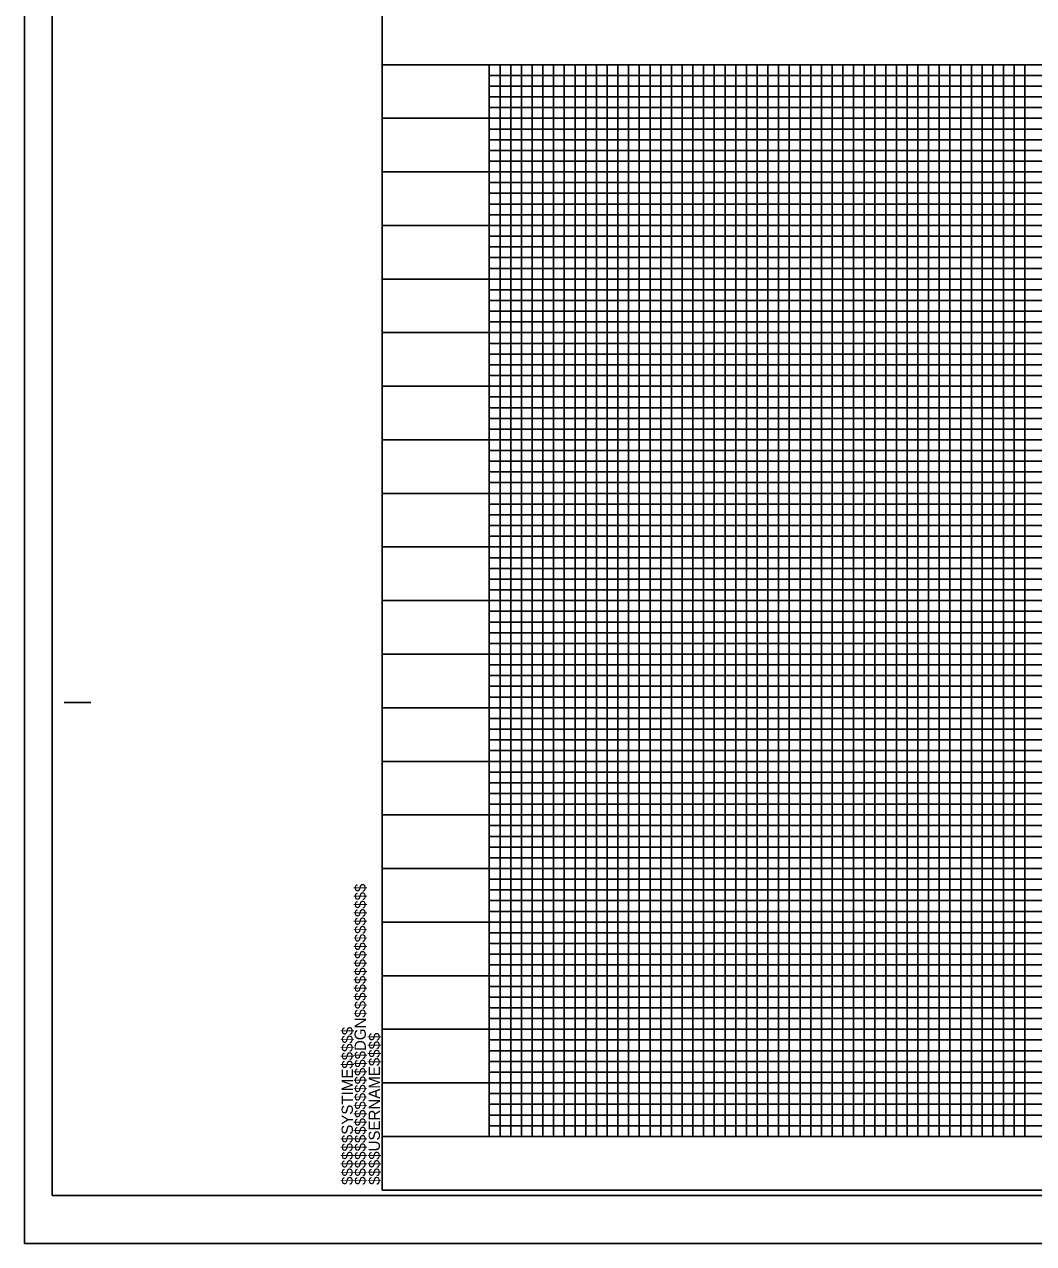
# Model space of a CAD drawing. Extents: x 553912 to 567693, y 512355 to 537539.
# Drawn here: x 565534 to 566005, y 513390 to 513959 of the extents above; entities that cross this region are included whole.
import ezdxf

# ---------------------------------------------------------------- set-up
doc = ezdxf.new("R2010")
doc.units = 0
for name, color, linetype in [('Sheet Cutting Line CELL', 7, 'Continuous'), ('Sheet DOT Grid CELL', 7, 'Continuous'), ('Sheet Layout Profile Border Port 2', 7, 'Continuous'), ('Sheet Plot Border Inside CELL', 7, 'Continuous'), ('Sheet Plot Border Outside CELL', 7, 'Continuous'), ('Sheet Profile CELL', 7, 'Continuous'), ('Sheet Profile Grid Major CELL', 7, 'Continuous'), ('Sheet Profile Grid Middle CELL', 7, 'Continuous'), ('Sheet Profile Grid Minor CELL', 7, 'Continuous')]:
    doc.layers.add(name, color=color, linetype=linetype)

msp = doc.modelspace()

# ---------------------------------------------------------------- linework, layer by layer
at = {"layer": 'Sheet Cutting Line CELL'}
for p, q in [((565534.35, 514489.72), (565534.35, 513389.72)), ((565534.35, 513389.72), (567218.35, 513389.72))]:
    msp.add_line(p, q, dxfattribs=at)
at = {"layer": 'Sheet DOT Grid CELL'}
for p, q in [((565701.35, 513939.72), (567201.24, 513939.72)), ((565751.35, 513939.72), (565751.35, 513439.72)), ((565801.35, 513939.72), (565801.35, 513439.72)), ((565851.35, 513939.72), (565851.35, 513439.72)), ((565901.35, 513939.72), (565901.35, 513439.72)), ((565951.35, 513939.72), (565951.35, 513439.72)), ((566001.35, 513939.72), (566001.35, 513439.72)), ((565701.35, 513889.72), (567201.24, 513889.72)), ((565701.35, 513839.72), (567201.24, 513839.72)), ((565701.35, 513789.72), (567201.24, 513789.72)), ((565701.35, 513739.72), (567201.24, 513739.72)), ((565701.35, 513689.72), (567201.24, 513689.72)), ((565701.35, 513639.72), (567201.24, 513639.72)), ((565701.35, 513589.72), (567201.24, 513589.72)), ((565701.35, 513539.72), (567201.24, 513539.72)), ((565701.35, 513489.72), (567201.24, 513489.72))]:
    msp.add_line(p, q, dxfattribs=at)
at = {"layer": 'Sheet Layout Profile Border Port 2'}
msp.add_lwpolyline([(565751.35, 513939.72), (567151.35, 513939.72), (567151.35, 513439.72), (565751.35, 513439.72)], close=True, dxfattribs=at)
at = {"layer": 'Sheet Plot Border Inside CELL'}
msp.add_lwpolyline([(565547.35, 513412.17), (567213.85, 513412.17), (567213.85, 514467.27), (565547.35, 514467.27)], close=True, dxfattribs=at)
at = {"layer": 'Sheet Plot Border Outside CELL'}
msp.add_lwpolyline([(565534.35, 513389.72), (567218.35, 513389.72), (567218.35, 514489.72), (565534.35, 514489.72)], close=True, dxfattribs=at)
at = {"layer": 'Sheet Profile CELL'}
for p, q in [((565701.35, 513939.72), (567201.35, 513939.72)), ((565552.85, 513642.22), (565565.35, 513642.22)), ((567201.35, 513439.72), (565701.35, 513439.72)), ((565701.35, 513414.72), (567201.35, 513414.72)), ((565701.35, 513414.72), (565701.35, 513414.72)), ((565701.35, 513414.72), (565701.35, 513414.72)), ((565701.35, 513414.72), (565701.35, 513414.72)), ((565701.35, 513414.72), (565701.35, 513414.72)), ((565701.35, 513414.72), (565701.35, 513414.72)), ((565701.35, 513414.72), (565701.35, 513414.72)), ((565701.35, 513414.72), (565701.35, 513414.72))]:
    msp.add_line(p, q, dxfattribs=at)
msp.add_lwpolyline([(567201.35, 514464.72), (565701.35, 514464.72), (565701.35, 513414.72), (567201.35, 513414.72)], close=True, dxfattribs=at)
msp.add_lwpolyline([(565738.85, 513414.72), (565738.85, 513414.72)], dxfattribs=at)
at = {"layer": 'Sheet Profile Grid Major CELL'}
msp.add_line((565701.35, 513439.72), (565701.35, 513439.72), dxfattribs=at)
for points in [[(565751.35, 513939.72), (565751.35, 513439.72), (565801.35, 513439.72), (565801.35, 513939.72), (565851.35, 513939.72), (565851.35, 513439.72), (565901.35, 513439.72), (565901.35, 513939.72), (565951.35, 513939.72), (565951.35, 513439.72), (566001.35, 513439.72), (566001.35, 513939.72), (566051.35, 513939.72)], [(567201.35, 513889.72), (565701.35, 513889.72)], [(567201.35, 513839.72), (565701.35, 513839.72), (565701.35, 513789.72), (567201.35, 513789.72)], [(567201.35, 513739.72), (565701.35, 513739.72), (565701.35, 513689.72), (567201.35, 513689.72)], [(567201.35, 513639.72), (565701.35, 513639.72), (565701.35, 513589.72), (567201.35, 513589.72)], [(567201.35, 513539.72), (565701.35, 513539.72), (565701.35, 513539.72), (565701.35, 513489.72), (567201.35, 513489.72)], [(567201.35, 513439.72), (565701.35, 513439.72)]]:
    msp.add_lwpolyline(points, dxfattribs=at)
at = {"layer": 'Sheet Profile Grid Middle CELL'}
for points in [[(565726.35, 513939.72), (565776.35, 513939.72), (565776.35, 513439.72), (565826.35, 513439.72), (565826.35, 513939.72), (565876.35, 513939.72), (565876.35, 513439.72), (565926.35, 513439.72), (565926.35, 513939.72), (565976.35, 513939.72), (565976.35, 513439.72), (566026.35, 513439.72)], [(565701.35, 513914.72), (567201.35, 513914.72)], [(567201.35, 513864.72), (565701.35, 513864.72), (565701.35, 513814.72), (567201.35, 513814.72)], [(567201.35, 513764.72), (565701.35, 513764.72), (565701.35, 513714.72), (567201.35, 513714.72)], [(567201.35, 513664.72), (565701.35, 513664.72), (565701.35, 513614.72), (567201.35, 513614.72)], [(567201.35, 513564.72), (565701.35, 513564.72), (565701.35, 513514.72), (567201.35, 513514.72)], [(567201.35, 513464.72), (565701.35, 513464.72)]]:
    msp.add_lwpolyline(points, dxfattribs=at)
at = {"layer": 'Sheet Profile Grid Minor CELL'}
for p, q in [((565751.35, 513934.72), (567151.35, 513934.72)), ((567151.35, 513929.72), (565751.35, 513929.72)), ((565751.35, 513924.72), (567151.35, 513924.72)), ((567151.35, 513919.72), (565751.35, 513919.72)), ((565751.35, 513909.72), (567151.35, 513909.72)), ((567151.35, 513904.72), (565751.35, 513904.72)), ((565751.35, 513899.72), (567151.35, 513899.72)), ((567151.35, 513894.72), (565751.35, 513894.72)), ((565751.35, 513884.72), (567151.35, 513884.72)), ((567151.35, 513879.72), (565751.35, 513879.72)), ((565751.35, 513874.72), (567151.35, 513874.72)), ((567151.35, 513869.72), (565751.35, 513869.72)), ((565751.35, 513859.72), (567151.35, 513859.72)), ((567151.35, 513854.72), (565751.35, 513854.72)), ((565751.35, 513849.72), (567151.35, 513849.72)), ((567151.35, 513844.72), (565751.35, 513844.72)), ((565751.35, 513834.72), (567151.35, 513834.72)), ((567151.35, 513829.72), (565751.35, 513829.72)), ((565751.35, 513824.72), (567151.35, 513824.72)), ((567151.35, 513819.72), (565751.35, 513819.72)), ((565751.35, 513809.72), (567151.35, 513809.72)), ((567151.35, 513804.72), (565751.35, 513804.72)), ((565751.35, 513799.72), (567151.35, 513799.72)), ((567151.35, 513794.72), (565751.35, 513794.72)), ((565751.35, 513784.72), (567151.35, 513784.72)), ((567151.35, 513779.72), (565751.35, 513779.72)), ((565751.35, 513774.72), (567151.35, 513774.72)), ((567151.35, 513769.72), (565751.35, 513769.72)), ((565751.35, 513759.72), (567151.35, 513759.72)), ((567151.35, 513754.72), (565751.35, 513754.72)), ((565751.35, 513749.72), (567151.35, 513749.72)), ((567151.35, 513744.72), (565751.35, 513744.87)), ((565751.35, 513734.72), (567151.35, 513734.72)), ((567151.35, 513729.72), (565751.35, 513729.72)), ((565751.35, 513724.72), (567151.35, 513724.72)), ((567151.35, 513719.72), (565751.35, 513719.72)), ((565751.35, 513709.72), (567151.35, 513709.72)), ((567151.35, 513704.72), (565751.35, 513704.72)), ((565751.35, 513699.72), (567151.35, 513699.72)), ((567151.35, 513694.72), (565751.35, 513694.72)), ((565751.35, 513684.72), (567151.35, 513684.72)), ((567151.35, 513679.72), (565751.35, 513679.72)), ((565751.35, 513674.72), (567151.35, 513674.72)), ((567151.35, 513669.72), (565751.35, 513669.72)), ((565751.35, 513659.72), (567151.35, 513659.72)), ((567151.35, 513654.72), (565751.35, 513654.72)), ((565751.35, 513649.72), (567151.35, 513649.72)), ((567151.35, 513644.72), (565751.35, 513644.72)), ((565751.35, 513634.72), (567151.35, 513634.72)), ((567151.35, 513629.72), (565751.35, 513629.72)), ((565751.35, 513624.72), (567151.35, 513624.72)), ((567151.35, 513619.72), (565751.35, 513619.72)), ((565751.35, 513609.72), (567151.35, 513609.72)), ((567151.35, 513604.72), (565751.35, 513604.72)), ((565751.35, 513599.72), (567151.35, 513599.72)), ((567151.35, 513594.72), (565751.35, 513594.72)), ((565751.35, 513584.72), (567151.35, 513584.72)), ((567151.35, 513579.72), (565751.35, 513579.72)), ((565751.35, 513574.72), (567151.35, 513574.72)), ((567151.35, 513569.72), (565751.35, 513569.72)), ((565751.35, 513559.72), (567151.35, 513559.72)), ((567151.35, 513554.72), (565751.35, 513554.72)), ((565751.35, 513549.72), (567151.35, 513549.72)), ((567151.35, 513544.72), (565751.35, 513544.72)), ((565751.35, 513534.72), (567151.35, 513534.72)), ((567151.35, 513529.72), (565751.35, 513529.72)), ((565751.35, 513524.72), (567151.35, 513524.72)), ((567151.35, 513519.72), (565751.35, 513519.72)), ((565751.35, 513509.72), (567151.35, 513509.72)), ((567151.35, 513504.72), (565751.35, 513504.72)), ((565751.35, 513499.72), (567151.35, 513499.72)), ((567151.35, 513494.72), (565751.35, 513494.72)), ((565751.35, 513484.72), (567151.35, 513484.72)), ((567151.35, 513479.72), (565751.35, 513479.72)), ((565751.35, 513474.72), (567151.35, 513474.72)), ((567151.35, 513469.72), (565751.35, 513469.72)), ((565751.35, 513459.72), (567151.35, 513459.72)), ((567151.35, 513454.72), (565751.35, 513454.72)), ((565751.35, 513449.72), (567151.35, 513449.72)), ((565751.35, 513444.72), (567151.35, 513444.72))]:
    msp.add_line(p, q, dxfattribs=at)
for points in [[(565751.35, 513939.72), (565756.35, 513939.72), (565756.35, 513439.72), (565761.35, 513439.72), (565761.35, 513939.72), (565766.35, 513939.72), (565766.35, 513439.72), (565771.35, 513439.72), (565771.35, 513939.72), (565781.35, 513939.72), (565781.35, 513439.72), (565786.35, 513439.72), (565786.35, 513939.72), (565791.35, 513939.72), (565791.35, 513439.72), (565796.35, 513439.72), (565806.35, 513439.72), (565811.35, 513439.72), (565811.35, 513939.72), (565816.35, 513939.72), (565816.35, 513439.72), (565821.35, 513439.72), (565821.35, 513939.72), (565831.35, 513939.72), (565831.35, 513439.72), (565836.35, 513439.72), (565836.35, 513939.72), (565841.35, 513939.72), (565841.35, 513439.72), (565846.35, 513439.72), (565846.35, 513939.72), (565856.35, 513939.72), (565856.35, 513439.72), (565861.35, 513439.72), (565861.35, 513939.72), (565866.35, 513939.72), (565866.35, 513439.72), (565871.35, 513439.72), (565871.35, 513939.72), (565881.35, 513939.72), (565881.35, 513439.72), (565886.35, 513439.72), (565886.35, 513939.72), (565891.35, 513939.72), (565891.35, 513439.72), (565896.35, 513439.72), (565896.35, 513939.72), (565906.35, 513939.72), (565906.35, 513439.72), (565911.35, 513439.72), (565911.35, 513939.72), (565916.35, 513939.72), (565916.35, 513439.72), (565921.35, 513439.72), (565921.35, 513939.72), (565931.35, 513939.72), (565931.35, 513439.72), (565936.35, 513439.72), (565936.35, 513939.72), (565941.35, 513939.72), (565941.35, 513439.72), (565946.35, 513439.72), (565946.35, 513939.72), (565956.35, 513939.72), (565956.35, 513439.72), (565961.35, 513439.72), (565961.35, 513939.72), (565966.35, 513939.72), (565966.35, 513439.72)], [(565796.35, 513439.72), (565796.35, 513939.72), (565806.35, 513939.72), (565806.35, 513439.72)], [(565966.35, 513439.72), (565971.35, 513439.72), (565971.35, 513939.72), (565981.35, 513939.72), (565981.35, 513439.72), (565986.35, 513439.72), (565986.35, 513939.72), (565991.35, 513939.72), (565991.35, 513439.72), (565996.35, 513439.72), (565996.35, 513939.72), (566006.35, 513939.72)]]:
    msp.add_lwpolyline(points, dxfattribs=at)

# ---------------------------------------------------------------- texts
at = {"layer": 'Sheet Profile CELL'}
for s, p in [('$$$$$$$$$$$$$$$$DGN$$$$$$$$$$$$$$$$', (565693.72, 513417.09)), ('$$$$$$SYSTIME$$$$$', (565687.67, 513417.09)), ('$$$$USERNAME$$$$', (565700.29, 513417.11))]:
    msp.add_text(s, height=5.25, rotation=90, dxfattribs=at).set_placement(p)

doc.saveas('drawing.dxf')
